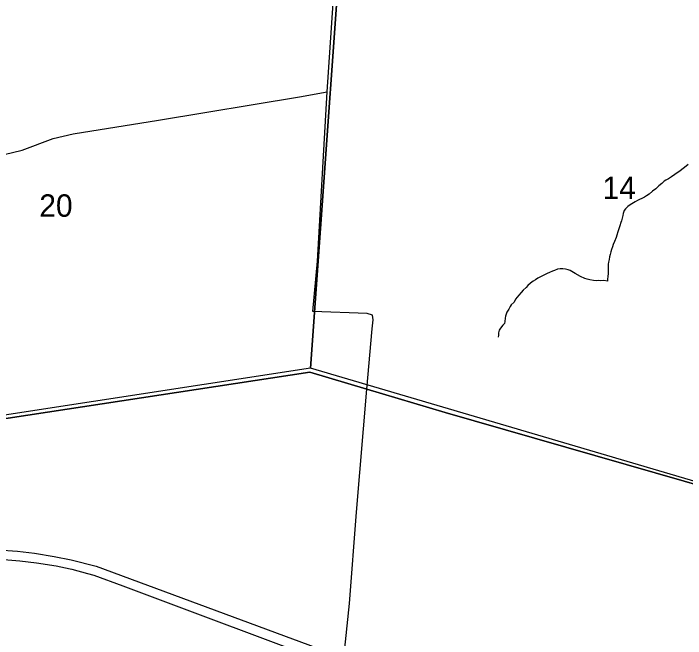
# Model space of a CAD drawing. Extents: x 0 to 34, y 0 to 22.
# Drawn here: x 12.335 to 13.591, y 14.81 to 15.978 of the extents above; entities that cross this region are included whole.
import ezdxf

# ---------------------------------------------------------------- set-up
doc = ezdxf.new("R2010")
doc.units = 0
for name, color, linetype in [('GM_X_City_Street', 7, 'Continuous'), ('GM_X_County_Road', 7, 'Continuous'), ('GM_X_Interstate_Route', 7, 'Continuous'), ('GM_X_Minor_River', 7, 'Continuous'), ('GM_X_Section', 7, 'Continuous'), ('GM_X_Section_Text', 7, 'Continuous'), ('GM_X_Township_Road', 7, 'Continuous'), ('SC_Scratch1', 7, 'Continuous'), ('SH_Cut_Line', 7, 'Continuous')]:
    doc.layers.add(name, color=color, linetype=linetype)

msp = doc.modelspace()

# ---------------------------------------------------------------- linework, layer by layer
at = {"layer": 'GM_X_City_Street'}
for points in [[(12.9955, 15.2757), (13.0054, 15.3889), (13.0069, 15.4053), (13.0055, 15.414), (12.9957, 15.4172), (12.8946, 15.421), (12.9032, 15.5147), (12.9212, 15.8314)], [(12.9626, 14.8755), (12.9762, 15.0462), (12.9955, 15.2757)], [(12.9623, 13.6851), (12.8994, 13.8085), (12.8715, 13.8632), (12.8578, 13.8901), (12.8505, 13.9105), (12.8446, 13.9407), (12.8435, 13.9677), (12.8438, 13.9783), (12.8457, 13.9893), (12.8504, 14.009), (12.8817, 14.1527), (12.8925, 14.1925), (12.8989, 14.2158), (12.9063, 14.2462), (12.9222, 14.3585), (12.9265, 14.415), (12.9313, 14.4767), (12.9351, 14.5269), (12.9392, 14.5807), (12.95, 14.7552), (12.952, 14.774), (12.9626, 14.8755)]]:
    msp.add_lwpolyline(points, dxfattribs=at)
at = {"layer": 'GM_X_County_Road'}
msp.add_lwpolyline([(12.9212, 15.8314), (12.9324, 15.9965), (12.9371, 16.0574), (12.9393, 16.0861), (12.9447, 16.1459), (12.9589, 16.3091), (12.9597, 16.324), (12.9594, 16.331), (12.9577, 16.3401), (12.956, 16.3469), (12.9542, 16.3504), (12.9514, 16.356), (12.9471, 16.3623), (12.9448, 16.3654)], dxfattribs=at)
at = {"layer": 'GM_X_Interstate_Route'}
msp.add_line((12.444, 14.9395), (12.4734, 14.9318), dxfattribs=at)
for points in [[(12.3052, 14.9757), (12.3424, 14.9736), (12.374, 14.9694), (12.4109, 14.9634), (12.4427, 14.957), (12.4894, 14.9451), (12.952, 14.774)], [(11.8486, 14.8669), (11.9474, 14.8941), (11.9918, 14.9072), (12.0845, 14.9332), (12.1403, 14.9455), (12.1876, 14.9533), (12.2297, 14.957), (12.2722, 14.9585), (12.309, 14.9582), (12.3467, 14.9555), (12.3779, 14.9518), (12.4148, 14.9459), (12.4411, 14.9403), (12.444, 14.9395)], [(12.4734, 14.9318), (12.4852, 14.9287), (12.5394, 14.9085)], [(12.5394, 14.9085), (12.95, 14.7552), (13.1689, 14.674), (13.2535, 14.6468), (13.3116, 14.6293), (13.3384, 14.6225)]]:
    msp.add_lwpolyline(points, dxfattribs=at)
at = {"layer": 'GM_X_Minor_River'}
for points in [[(13.5958, 15.6952), (13.5888, 15.6901), (13.5838, 15.6861), (13.5803, 15.6831), (13.5749, 15.6799), (13.571, 15.6766), (13.5644, 15.6722), (13.559, 15.6689), (13.5539, 15.6661), (13.5505, 15.6643), (13.5465, 15.6602), (13.5411, 15.6558), (13.5352, 15.6503), (13.529, 15.6455), (13.5228, 15.64), (13.5177, 15.6367), (13.5142, 15.6342), (13.5089, 15.6321), (13.505, 15.6303), (13.5008, 15.6281), (13.4969, 15.626), (13.4934, 15.6242), (13.4872, 15.6202), (13.483, 15.6169), (13.4787, 15.6128), (13.4763, 15.6095), (13.4742, 15.6042), (13.4733, 15.6001), (13.4724, 15.5955), (13.4708, 15.5903), (13.4699, 15.5869), (13.4678, 15.5809), (13.467, 15.5771), (13.4657, 15.5737), (13.4645, 15.5696), (13.4624, 15.5635), (13.4611, 15.5594), (13.4582, 15.5515), (13.4558, 15.5463), (13.4545, 15.5417), (13.4525, 15.5365), (13.4512, 15.5323), (13.4496, 15.5274), (13.4487, 15.5233), (13.4478, 15.5184), (13.4465, 15.5131), (13.446, 15.5093), (13.4463, 15.5059), (13.4459, 15.4922), (13.4453, 15.4861), (13.4448, 15.4812), (13.4451, 15.4778), (13.4383, 15.4787), (13.4326, 15.4785), (13.4284, 15.479), (13.4242, 15.4784), (13.4189, 15.4786), (13.4117, 15.4799), (13.4072, 15.4812), (13.4023, 15.4825), (13.3944, 15.4862)], [(13.3944, 15.4862), (13.3847, 15.4918), (13.3783, 15.4954), (13.3749, 15.4974), (13.3712, 15.499), (13.3667, 15.5003), (13.3614, 15.5009), (13.3564, 15.5006), (13.3515, 15.5), (13.3461, 15.4975), (13.3419, 15.4965), (13.3365, 15.494), (13.3322, 15.4919), (13.3245, 15.4883), (13.3199, 15.4858), (13.3149, 15.4833), (13.3102, 15.4804), (13.3063, 15.4778), (13.3013, 15.4742), (13.2962, 15.4694), (13.2927, 15.4657), (13.2876, 15.4609), (13.2833, 15.4565), (13.279, 15.4513), (13.2731, 15.4442), (13.2702, 15.4386), (13.2651, 15.4335), (13.2628, 15.4301), (13.2603, 15.4252), (13.2571, 15.4196), (13.2546, 15.4121), (13.2538, 15.4083), (13.2532, 15.4026), (13.2527, 15.3985), (13.2492, 15.3952), (13.2449, 15.39), (13.2425, 15.3859), (13.2412, 15.3813), (13.2414, 15.3768), (13.2406, 15.373)]]:
    msp.add_lwpolyline(points, dxfattribs=at)
at = {"layer": 'GM_X_Section'}
for points in [[(11.9608, 16.1562), (12.9642, 16.3503), (12.8901, 15.3152), (11.8797, 15.1603)], [(12.9642, 16.3503), (14.0511, 15.9925), (13.9657, 14.9981), (12.8901, 15.3152)]]:
    msp.add_lwpolyline(points, close=True, dxfattribs=at)
at = {"layer": 'GM_X_Township_Road'}
msp.add_lwpolyline([(12.3178, 15.7142), (12.3509, 15.7223), (12.4093, 15.744), (12.4463, 15.753), (12.6059, 15.7785), (12.8694, 15.8221), (12.9212, 15.8314)], dxfattribs=at)
at = {"layer": 'SC_Scratch1'}
for points in [[(11.871, 15.1527), (12.8889, 15.308), (12.9952, 15.2762), (13.1413, 15.2326), (13.9262, 15.0068), (13.9652, 14.9956), (14.0118, 15.5668), (14.0411, 15.8502), (14.0483, 15.9927)], [(15.1228, 15.0411), (14.9881, 15.0623), (14.5054, 15.0324), (14.0783, 15.001), (13.9652, 14.9956), (13.9262, 15.0068), (13.1413, 15.2326), (12.9952, 15.2762), (12.8889, 15.308), (11.871, 15.1527)]]:
    msp.add_lwpolyline(points, dxfattribs=at)
at = {"layer": 'SH_Cut_Line'}
for points in [[(11.871, 15.1527), (12.8889, 15.308), (12.9952, 15.2762), (13.1413, 15.2326), (13.9262, 15.0068), (13.9652, 14.9956), (14.0783, 15.001), (14.5054, 15.0324), (14.9881, 15.0623), (15.1228, 15.0411), (15.3254, 15.0063), (15.5154, 14.9734), (15.5826, 14.9621), (15.7547, 14.933), (15.8407, 14.9188), (15.9769, 14.894), (16.1, 14.8738), (16.1, 20.2361)], [(9.3, 13.4361), (16.1, 13.4361), (16.1, 14.8738), (15.9769, 14.894), (15.8407, 14.9188), (15.7547, 14.933), (15.5826, 14.9621), (15.5154, 14.9734), (15.3254, 15.0063), (15.1228, 15.0411), (14.9881, 15.0623), (14.5054, 15.0324), (14.0783, 15.001), (13.9652, 14.9956), (13.9262, 15.0068), (13.1413, 15.2326), (12.9952, 15.2762), (12.8889, 15.308), (11.871, 15.1527)]]:
    msp.add_lwpolyline(points, dxfattribs=at)

# ---------------------------------------------------------------- texts
at = {"layer": 'GM_X_Section_Text'}
for s, p in [('14', (13.4357, 15.6312)), ('20', (12.3832, 15.5979))]:
    msp.add_text(s, height=0.04186, rotation=0, dxfattribs=at).set_placement(p)

doc.saveas('drawing.dxf')
